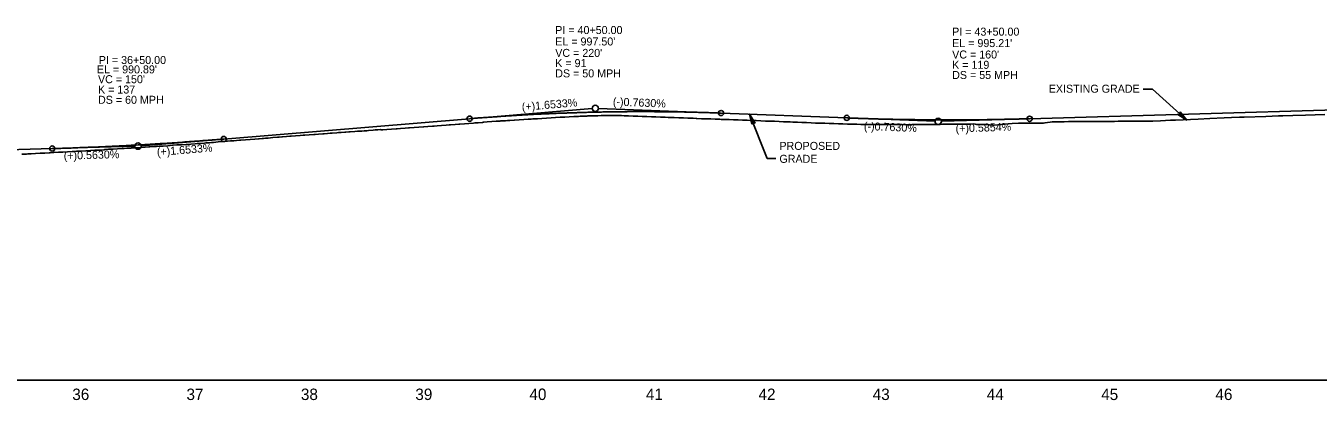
# Model space of a CAD drawing. Extents: x 1615624 to 1632571, y 894455 to 913418.
# Drawn here: x 1626082 to 1627212, y 901317 to 901644 of the extents above; entities that cross this region are included whole.
import ezdxf

# ---------------------------------------------------------------- set-up
doc = ezdxf.new("R2010")
doc.units = 0
for name, color, linetype in [('Exist Profile Cell', 7, 'Continuous'), ('Exist Vertical Profile Ground Line', 7, 'Continuous'), ('Exist Vertical Profile Horizontal Axis Label Major', 7, 'Continuous'), ('Prop Terminator CELL', 7, 'Continuous'), ('Prop Vertical Profile Curve Label', 7, 'Continuous'), ('Prop Vertical Profile Grade', 7, 'Continuous'), ('Prop Vertical Profile Grade Label', 7, 'Continuous'), ('Prop VPI Label', 7, 'Continuous')]:
    doc.layers.add(name, color=color, linetype=linetype)

msp = doc.modelspace()

# ---------------------------------------------------------------- linework, layer by layer
at = {"layer": 'Exist Profile Cell'}
for q in [(1628880.1, 901334.4), (1628929.9, 901334.4)]:
    msp.add_line((1623529.9, 901334.4), q, dxfattribs=at)
at = {"layer": 'Exist Vertical Profile Ground Line'}
msp.add_lwpolyline([(1626078.3, 901531.8), (1626082.3, 901532), (1626083.4, 901532.1), (1626086.3, 901532.2), (1626090.3, 901532.4), (1626094.3, 901532.6), (1626098.3, 901532.8), (1626102.3, 901533), (1626103.1, 901533.1), (1626105.7, 901533.2), (1626106.3, 901533.3), (1626110.3, 901533.5), (1626114.2, 901533.7), (1626118.2, 901533.9), (1626122.2, 901534.1), (1626124.2, 901534.2), (1626126.2, 901534.4), (1626128.4, 901534.5), (1626130.2, 901534.6), (1626134.2, 901534.8), (1626138.2, 901535.1), (1626142.2, 901535.3), (1626145.8, 901535.5), (1626146.2, 901535.5), (1626150.2, 901535.8), (1626151, 901535.9), (1626154.2, 901536.1), (1626158.1, 901536.3), (1626162.1, 901536.6), (1626166.1, 901536.8), (1626167.7, 901536.9), (1626170.1, 901537), (1626173.7, 901537.2), (1626174.1, 901537.3), (1626178.1, 901537.5), (1626182.1, 901537.8), (1626186.1, 901538.1), (1626189.5, 901538.3), (1626190.1, 901538.3), (1626194.1, 901538.5), (1626196.2, 901538.6), (1626198, 901538.8), (1626202, 901539), (1626206, 901539.3), (1626210, 901539.6), (1626210.6, 901539.6), (1626214, 901539.9), (1626218, 901540.1), (1626222, 901540.4), (1626226, 901540.7), (1626230, 901541), (1626231.6, 901541.2), (1626234, 901541.3), (1626238, 901541.6), (1626239.3, 901541.7), (1626241.9, 901541.9), (1626244.3, 901542.1), (1626245.9, 901542.2), (1626249.9, 901542.6), (1626253.9, 901542.9), (1626257.9, 901543.2), (1626258.3, 901543.2), (1626260.9, 901543.4), (1626261.9, 901543.5), (1626263.6, 901543.6), (1626266, 901543.8), (1626268.6, 901544), (1626269.9, 901544.1), (1626273.9, 901544.4), (1626277.9, 901544.8), (1626282, 901545.1), (1626285.2, 901545.3), (1626285.8, 901545.4), (1626288.5, 901545.6), (1626289.8, 901545.7), (1626291.5, 901545.8), (1626293.8, 901546), (1626297.8, 901546.3), (1626301.8, 901546.7), (1626303.5, 901546.8), (1626305.8, 901547), (1626306.4, 901547.1), (1626309.8, 901547.3), (1626312.8, 901547.5), (1626313.8, 901547.6), (1626317.8, 901547.9), (1626321.8, 901548.2), (1626324.3, 901548.4), (1626325.7, 901548.5), (1626329.7, 901548.8), (1626333.7, 901549), (1626335, 901549.1), (1626337.7, 901549.3), (1626341.7, 901549.6), (1626342.7, 901549.7), (1626345.7, 901549.9), (1626347.9, 901550.1), (1626349.7, 901550.2), (1626353.7, 901550.6), (1626355.3, 901550.7), (1626357.7, 901550.9), (1626360.7, 901551.1), (1626361.7, 901551.2), (1626364.3, 901551.3), (1626365.6, 901551.4), (1626369.6, 901551.7), (1626371.9, 901551.9), (1626373.6, 901552), (1626375.6, 901552.1), (1626377.6, 901552.3), (1626380.1, 901552.4), (1626381.6, 901552.6), (1626385.6, 901552.9), (1626387.5, 901553), (1626389.6, 901553.1), (1626392.1, 901553.3), (1626392.5, 901553.1), (1626393.1, 901553.1), (1626393.7, 901553.2), (1626394, 901553.2), (1626397.6, 901553.4), (1626401.6, 901553.7), (1626405.6, 901554), (1626406.7, 901554.1), (1626409.5, 901554.3), (1626413.5, 901554.6), (1626416.5, 901554.8), (1626417.5, 901554.9), (1626421.5, 901555.1), (1626425.5, 901555.4), (1626429.5, 901555.7), (1626429.9, 901555.7), (1626433.5, 901556), (1626437.5, 901556.3), (1626439, 901556.4), (1626441.5, 901556.6), (1626445.5, 901556.9), (1626449.4, 901557.2), (1626452.2, 901557.4), (1626453.4, 901557.5), (1626457.4, 901557.8), (1626460.6, 901558), (1626461.4, 901558.1), (1626465.4, 901558.4), (1626469.4, 901558.7), (1626473.4, 901559.1), (1626474.5, 901559.2), (1626477.4, 901559.4), (1626481.4, 901559.7), (1626482.2, 901559.8), (1626485.4, 901560), (1626489.4, 901560.3), (1626493.3, 901560.6), (1626496.5, 901560.8), (1626497.3, 901560.9), (1626501.3, 901561.1), (1626503, 901561.3), (1626505.3, 901561.4), (1626508.9, 901561.6), (1626509.3, 901561.6), (1626513.3, 901561.9), (1626517.3, 901562.2), (1626521.3, 901562.4), (1626523.8, 901562.6), (1626525.3, 901562.7), (1626529.3, 901562.9), (1626533.2, 901563.1), (1626537.2, 901563.4), (1626541.2, 901563.6), (1626545.2, 901563.9), (1626549.2, 901564.1), (1626553.2, 901564.3), (1626557.2, 901564.5), (1626561.2, 901564.8), (1626562.3, 901564.8), (1626565.2, 901564.9), (1626566.6, 901565), (1626569.2, 901565.1), (1626572.7, 901565.2), (1626573.2, 901565.3), (1626576, 901565.3), (1626577.1, 901565.4), (1626581.1, 901565.5), (1626582.1, 901565.5), (1626585.1, 901565.6), (1626589.1, 901565.7), (1626591, 901565.7), (1626593.1, 901565.7), (1626593.9, 901565.7), (1626597.1, 901565.6), (1626601.1, 901565.6), (1626602.8, 901565.6), (1626605.1, 901565.5), (1626609.1, 901565.3), (1626613.1, 901565.2), (1626617, 901565), (1626621, 901564.9), (1626621.6, 901564.8), (1626624.6, 901564.8), (1626625, 901564.7), (1626629, 901564.6), (1626633, 901564.4), (1626637, 901564.3), (1626641, 901564.1), (1626643.6, 901564), (1626645, 901564), (1626646.3, 901563.9), (1626649, 901563.8), (1626653, 901563.7), (1626657, 901563.5), (1626660.9, 901563.4), (1626664.9, 901563.3), (1626665.6, 901563.2), (1626668.2, 901563.1), (1626668.9, 901563.1), (1626672.9, 901562.9), (1626676.9, 901562.8), (1626680.9, 901562.7), (1626684.9, 901562.5), (1626687.6, 901562.4), (1626688.9, 901562.4), (1626690, 901562.3), (1626692.9, 901562.2), (1626696.9, 901562.1), (1626700.8, 901561.9), (1626704.8, 901561.8), (1626708.8, 901561.6), (1626711.1, 901561.5), (1626712.8, 901561.5), (1626716.8, 901561.3), (1626720.8, 901561.2), (1626724.8, 901561), (1626728.8, 901560.8), (1626729.8, 901560.8), (1626732.2, 901560.7), (1626732.8, 901560.7), (1626736.8, 901560.6), (1626740.8, 901560.4), (1626744.7, 901560.2), (1626748.7, 901560), (1626750.4, 901560), (1626752.8, 901559.9), (1626755.2, 901559.9), (1626756.7, 901559.8), (1626760.7, 901559.6), (1626764.7, 901559.5), (1626768.7, 901559.3), (1626772.7, 901559.1), (1626773.3, 901559.1), (1626776, 901559), (1626776.7, 901559), (1626780.7, 901558.9), (1626784.6, 901558.7), (1626788.6, 901558.6), (1626792.6, 901558.4), (1626794.4, 901558.3), (1626796.6, 901558.3), (1626800.6, 901558.2), (1626804.6, 901558.1), (1626808.6, 901558), (1626812.3, 901557.9), (1626812.6, 901557.9), (1626815.4, 901557.9), (1626816.6, 901557.9), (1626820.6, 901557.9), (1626824.6, 901557.8), (1626828.5, 901557.8), (1626832.5, 901557.8), (1626833.3, 901557.8), (1626836.5, 901557.8), (1626840.5, 901557.7), (1626844.5, 901557.7), (1626848.5, 901557.7), (1626852.5, 901557.6), (1626854, 901557.6), (1626856.5, 901557.6), (1626857.1, 901557.7), (1626859, 901557.7), (1626860.5, 901557.7), (1626864.5, 901557.7), (1626868.4, 901557.8), (1626872.4, 901557.8), (1626876.4, 901557.9), (1626880.4, 901557.9), (1626881.6, 901557.9), (1626883.7, 901558), (1626884.4, 901558), (1626885.8, 901558), (1626888.4, 901558), (1626892.4, 901558.1), (1626896.4, 901558.1), (1626900.4, 901558.1), (1626904.4, 901558.2), (1626908, 901558.2), (1626908.4, 901558.2), (1626910.4, 901558.3), (1626912.3, 901558.1), (1626913.4, 901557.9), (1626915.9, 901557.7), (1626916.3, 901557.7), (1626920.3, 901557.8), (1626921.7, 901557.9), (1626924.3, 901557.6), (1626924.7, 901557.6), (1626927.3, 901557.3), (1626929, 901557.1), (1626944.7, 901558.8), (1626950.2, 901559), (1626956.3, 901559.1), (1626971.9, 901559), (1626973.4, 901559.4), (1626975.4, 901559.7), (1626977.8, 901559.9), (1626979.6, 901560), (1626986.7, 901560.1), (1626990.2, 901560.2), (1626994, 901560.3), (1627000.4, 901560.3), (1627006.2, 901560.4), (1627027.3, 901560.4), (1627033.4, 901560.5), (1627034.1, 901560.5), (1627037.4, 901560.6), (1627058.1, 901560.6), (1627067.6, 901560.8), (1627074.3, 901561.1), (1627083, 901561.5), (1627087.5, 901561.7), (1627107.3, 901562.6), (1627117.5, 901563), (1627130.1, 901563.6), (1627136.4, 901563.8), (1627143.5, 901564.1), (1627147.5, 901564.2), (1627166.6, 901564.9), (1627177.6, 901565.4), (1627181.5, 901565.5), (1627190, 901565.7), (1627201.1, 901566.1), (1627218.2, 901566.6)], dxfattribs=at)
at = {"layer": 'Prop Terminator CELL'}
for points in [[(1626716.8, 901558), (1626714.9, 901566.9), (1626719.7, 901559.1), (1626717.8, 901559.6)], [(1627091.7, 901568.9), (1627097.4, 901561.7), (1627089.6, 901566.6), (1627091.5, 901567)]]:
    msp.add_lwpolyline(points, close=True, dxfattribs=at)
at = {"layer": 'Prop Vertical Profile Curve Label'}
for centre in [(1626469.9, 901562.9), (1626689.9, 901567.8), (1626799.9, 901563.6), (1626959.9, 901562.8), (1626104.9, 901536.8), (1626254.9, 901545.1)]:
    msp.add_circle(centre, 2.25, dxfattribs=at)
at = {"layer": 'Prop Vertical Profile Grade'}
for p, q in [((1626959.9, 901562.8), (1627379.9, 901575.1)), ((1626254.9, 901545.1), (1626469.9, 901562.9)), ((1626689.9, 901567.8), (1626799.9, 901563.6)), ((1625829.9, 901529), (1626104.9, 901536.8))]:
    msp.add_line(p, q, dxfattribs=at)
for points in [[(1626469.9, 901562.9), (1626474.3, 901563.2), (1626478.7, 901563.6), (1626483.1, 901563.9), (1626487.5, 901564.2), (1626491.9, 901564.5), (1626496.3, 901564.8), (1626500.7, 901565.1), (1626505.1, 901565.4), (1626509.5, 901565.7), (1626513.9, 901566), (1626518.3, 901566.2), (1626522.7, 901566.5), (1626527.1, 901566.7), (1626531.5, 901566.9), (1626535.9, 901567.1), (1626540.3, 901567.3), (1626544.7, 901567.5), (1626549.1, 901567.7), (1626553.5, 901567.8), (1626557.9, 901568), (1626562.3, 901568.1), (1626566.7, 901568.3), (1626571.1, 901568.4), (1626575.5, 901568.5), (1626579.9, 901568.6), (1626584.3, 901568.7), (1626588.7, 901568.8), (1626593.1, 901568.9), (1626597.5, 901568.9), (1626601.9, 901569), (1626606.3, 901569), (1626610.7, 901569.1), (1626615.1, 901569.1), (1626619.5, 901569.1), (1626623.9, 901569.1), (1626628.3, 901569.1), (1626632.7, 901569), (1626637.1, 901569), (1626641.5, 901569), (1626645.9, 901568.9), (1626650.3, 901568.8), (1626654.7, 901568.8), (1626659.1, 901568.7), (1626663.5, 901568.6), (1626667.9, 901568.5), (1626672.3, 901568.3), (1626676.7, 901568.2), (1626681.1, 901568.1), (1626685.5, 901567.9), (1626689.9, 901567.8)], [(1626799.9, 901563.6), (1626803.1, 901563.4), (1626806.3, 901563.3), (1626809.5, 901563.2), (1626812.7, 901563.1), (1626815.9, 901563), (1626819.1, 901562.9), (1626822.3, 901562.8), (1626825.5, 901562.7), (1626828.7, 901562.6), (1626831.9, 901562.6), (1626835.1, 901562.5), (1626838.3, 901562.4), (1626841.5, 901562.3), (1626844.7, 901562.3), (1626847.9, 901562.2), (1626851.1, 901562.2), (1626854.3, 901562.1), (1626857.5, 901562.1), (1626860.7, 901562), (1626863.9, 901562), (1626867.1, 901561.9), (1626870.3, 901561.9), (1626873.5, 901561.9), (1626876.7, 901561.9), (1626879.9, 901561.9), (1626883.1, 901561.8), (1626886.3, 901561.8), (1626889.5, 901561.8), (1626892.7, 901561.8), (1626895.9, 901561.8), (1626899.1, 901561.8), (1626902.3, 901561.9), (1626905.5, 901561.9), (1626908.7, 901561.9), (1626911.9, 901561.9), (1626915.1, 901562), (1626918.3, 901562), (1626921.5, 901562), (1626924.7, 901562.1), (1626927.9, 901562.1), (1626931.1, 901562.2), (1626934.3, 901562.2), (1626937.5, 901562.3), (1626940.7, 901562.4), (1626943.9, 901562.4), (1626947.1, 901562.5), (1626950.3, 901562.6), (1626953.5, 901562.7), (1626956.7, 901562.8), (1626959.9, 901562.8)], [(1626104.9, 901536.8), (1626107.9, 901536.9), (1626110.9, 901536.9), (1626113.9, 901537), (1626116.9, 901537.1), (1626119.9, 901537.2), (1626122.9, 901537.3), (1626125.9, 901537.4), (1626128.9, 901537.6), (1626131.9, 901537.7), (1626134.9, 901537.8), (1626137.9, 901537.9), (1626140.9, 901538), (1626143.9, 901538.1), (1626146.9, 901538.3), (1626149.9, 901538.4), (1626152.9, 901538.5), (1626155.9, 901538.7), (1626158.9, 901538.8), (1626161.9, 901539), (1626164.9, 901539.1), (1626167.9, 901539.3), (1626170.9, 901539.4), (1626173.9, 901539.6), (1626176.9, 901539.7), (1626179.9, 901539.9), (1626182.9, 901540.1), (1626185.9, 901540.2), (1626188.9, 901540.4), (1626191.9, 901540.6), (1626194.9, 901540.8), (1626197.9, 901541), (1626200.9, 901541.1), (1626203.9, 901541.3), (1626206.9, 901541.5), (1626209.9, 901541.7), (1626212.9, 901541.9), (1626215.9, 901542.1), (1626218.9, 901542.3), (1626221.9, 901542.6), (1626224.9, 901542.8), (1626227.9, 901543), (1626230.9, 901543.2), (1626233.9, 901543.4), (1626236.9, 901543.7), (1626239.9, 901543.9), (1626242.9, 901544.1), (1626245.9, 901544.4), (1626248.9, 901544.6), (1626251.9, 901544.8), (1626254.9, 901545.1)]]:
    msp.add_spline(points, degree=3, dxfattribs=at)
at = {"layer": 'Prop VPI Label'}
for p, q in [((1627067.5, 901588.7), (1627059.2, 901588.7)), ((1627097.4, 901561.7), (1627067.5, 901588.7)), ((1626469.9, 901562.9), (1626577.2, 901571.7)), ((1626689.9, 901567.8), (1626582.7, 901571.8)), ((1626714.9, 901566.9), (1626730.3, 901528.2)), ((1626799.9, 901563.6), (1626877.2, 901560.6)), ((1626959.9, 901562.8), (1626882.7, 901560.6)), ((1626104.9, 901536.8), (1626177.2, 901538.8)), ((1626254.9, 901545.1), (1626182.7, 901539.1)), ((1626730.3, 901528.2), (1626737.8, 901528.2))]:
    msp.add_line(p, q, dxfattribs=at)
for centre in [(1626579.9, 901571.9), (1626879.9, 901560.5), (1626179.9, 901538.9)]:
    msp.add_circle(centre, 2.75, dxfattribs=at)

# ---------------------------------------------------------------- texts
at = {"layer": 'Exist Vertical Profile Horizontal Axis Label Major'}
for s, p in [('36', (1626122.4, 901316.9)), ('37', (1626222.3, 901316.9)), ('38', (1626322.4, 901316.9)), ('39', (1626422.5, 901316.9)), ('40', (1626522.3, 901316.9)), ('41', (1626624.2, 901316.9)), ('42', (1626722.7, 901316.9)), ('43', (1626822.6, 901316.9)), ('44', (1626922.4, 901316.9)), ('45', (1627022.5, 901316.9)), ('46', (1627122.4, 901316.9))]:
    msp.add_text(s, height=10, dxfattribs=at).set_placement(p)
at = {"layer": 'Prop Vertical Profile Curve Label'}
for s, p in [("VC = 220'", (1626544.9, 901616.9)), ("VC = 160'", (1626892.1, 901615.5)), ('K = 91', (1626544.9, 901608)), ('DS = 50 MPH', (1626544.9, 901599)), ('K = 119', (1626892.1, 901606.5)), ('DS = 55 MPH', (1626892.1, 901597.6)), ("VC = 150'", (1626144.9, 901593.9)), ('K = 137', (1626144.9, 901584.9)), ('DS = 60 MPH', (1626144.9, 901575.9))]:
    msp.add_text(s, height=7, dxfattribs=at).set_placement(p)
at = {"layer": 'Prop Vertical Profile Grade Label'}
for s, rotation, p in [('(-)0.7630%', 357.8154, (1626595.2, 901574.4)), ('(+)1.6533%', 4.7257, (1626515.9, 901569.7)), ('(-)0.7630%', 357.8154, (1626814.8, 901553)), ('(+)0.5854%', 1.6766, (1626895.2, 901550.9)), ('(+)1.6533%', 4.7257, (1626196.7, 901530.2)), ('(+)0.5630%', 1.6125, (1626115, 901527))]:
    msp.add_text(s, height=7, rotation=rotation, dxfattribs=at).set_placement(p)
at = {"layer": 'Prop VPI Label'}
for s, p in [('PI = 40+50.00', (1626544.9, 901636.9)), ('PI = 43+50.00', (1626892.1, 901635.5)), ("EL = 997.50'", (1626544.9, 901626.9)), ("EL = 995.21'", (1626892.1, 901625.5)), ('PI = 36+50.00', (1626145.6, 901610.7)), ("EL = 990.89'", (1626143.9, 901602.5)), ('EXISTING GRADE', (1626976.6, 901585.6)), ('PROPOSED ', (1626741, 901535.6)), ('GRADE', (1626741, 901524.3))]:
    msp.add_text(s, height=7, dxfattribs=at).set_placement(p)

doc.saveas('drawing.dxf')
